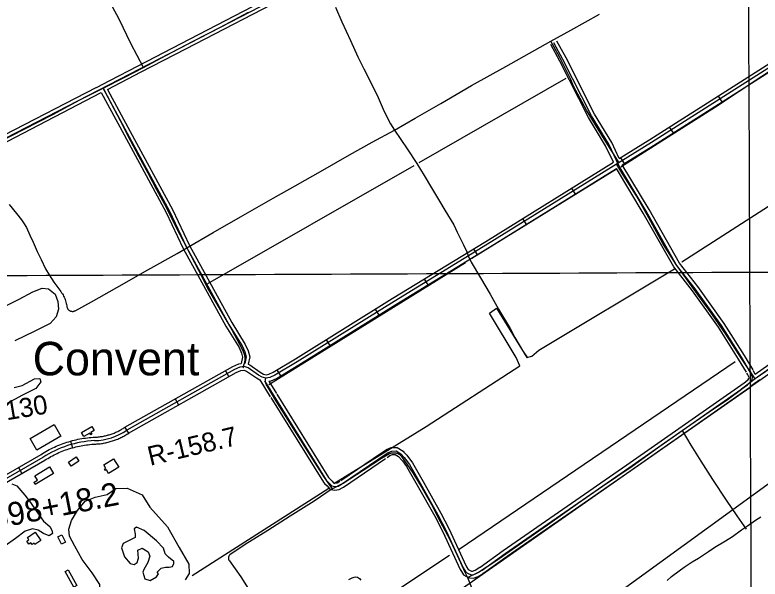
# Model space of a CAD drawing. Extents: x 3419139 to 3457078, y 540382 to 565875.
# Drawn here: x 3441162 to 3444391, y 550592 to 553037 of the extents above; entities that cross this region are included whole.
import ezdxf

# ---------------------------------------------------------------- set-up
doc = ezdxf.new("R2010")
doc.units = 0
for name, color, linetype in [('V-BLDG-OTLN', 7, 'Continuous'), ('V-DTCH-CNTR', 7, 'Continuous'), ('V-GRID-MAJR', 7, 'Continuous'), ('V-RIVR-RANG-IDEN', 7, 'Continuous'), ('V-ROAD-CNTR', 7, 'Continuous'), ('V-SITE-VEGE', 7, 'Continuous'), ('V-SURV-IDEN', 7, 'Continuous'), ('V-TOPO-GNAM-IDEN', 7, 'Continuous'), ('V-TOPO-SHOR', 7, 'Continuous')]:
    doc.layers.add(name, color=color, linetype=linetype)

msp = doc.modelspace()

# ---------------------------------------------------------------- linework, layer by layer
at = {"layer": 'V-BLDG-OTLN'}
for points in [[(3441227.6, 551200.6), (3441332, 551261.8), (3441361.2, 551211.9), (3441256.8, 551150.8)], [(3441450.4, 551226.7), (3441495, 551253.1), (3441505.3, 551235.7), (3441491.3, 551227.4), (3441495.3, 551220.6), (3441490.3, 551217.6), (3441485.9, 551225), (3441460.4, 551209.9)], [(3441393.4, 551098.6), (3441426.8, 551121.5), (3441439, 551103.7), (3441405.5, 551080.9)], [(3441546.7, 551086.4), (3441589.6, 551112.8), (3441612.1, 551076.4), (3441568, 551049.2), (3441558.4, 551064.8), (3441554.6, 551062.4), (3441550.7, 551068.6), (3441555.8, 551071.7)], [(3441248.2, 551039.8), (3441312.4, 551077.9), (3441329.3, 551049.4), (3441250.3, 551002.6), (3441244.9, 551011.7), (3441259.6, 551020.5)], [(3441215.9, 550772), (3441249, 550794.7), (3441273.6, 550758.9), (3441248.5, 550741.7), (3441244.8, 550747.1), (3441236.3, 550741.3), (3441230.6, 550749.6), (3441222.3, 550743.8), (3441214, 550756), (3441222.8, 550762)], [(3441365.3, 550783.1), (3441380.5, 550751.7), (3441363.6, 550743.5), (3441348.4, 550775)], [(3441393.1, 550631.6), (3441430.2, 550564.1), (3441417.2, 550556.9), (3441380.2, 550624.4)]]:
    msp.add_lwpolyline(points, close=True, dxfattribs=at)
at = {"layer": 'V-DTCH-CNTR'}
msp.add_line((3444370, 551459.4), (3444311.2, 551415), dxfattribs=at)
for points in [[(3441718.4, 552809.6), (3441664, 552912.9), (3441613, 553018.9), (3441556.2, 553127.4), (3441520.5, 553196), (3441525.6, 553201.3), (3441530.6, 553206.7), (3441535.4, 553212.3), (3441540.1, 553217.9), (3441544.6, 553223.7), (3441548.9, 553229.7), (3441553.1, 553235.7), (3441557.1, 553241.8), (3441561, 553248.1), (3441564.6, 553254.5), (3441568.1, 553260.9), (3441571.4, 553267.5), (3441574.5, 553274.1), (3441577.5, 553280.9)], [(3442551.4, 553070.8), (3442579.2, 553007.1), (3442615.7, 552925.7), (3442647.4, 552855.6), (3442674, 552803.6), (3442703.2, 552747.5), (3442735.5, 552678.8), (3442761.5, 552617.8), (3442789.6, 552565), (3442806.8, 552537.6), (3442861.5, 552456.5), (3442903.8, 552393), (3442935.2, 552340.5), (3442967.2, 552287.7), (3443001.7, 552229.6), (3443025.6, 552191.1), (3443063.3, 552127.6), (3443079, 552095.1), (3443105.9, 552040.5), (3443120.4, 552009.5), (3443127.5, 551989.6), (3443139.2, 551965.6), (3443180, 551897.2), (3443221.7, 551826.5), (3443257.7, 551762.4), (3443307.5, 551677.4), (3443327.7, 551639.4), (3443361, 551582.6), (3443382.7, 551551.3)], [(3441101.3, 552489.6), (3441201.9, 552541.3), (3441325.8, 552605.9), (3441442.5, 552668.5), (3441543.7, 552719.2), (3441635.8, 552766.3), (3441718.4, 552809.6), (3441815.3, 552860.9), (3441934.8, 552923.5), (3442052.3, 552983.6), (3442174.8, 553048.5)], [(3442611.9, 552430.3), (3442710.5, 552484.9), (3442806.8, 552537.6), (3442896.5, 552588.9), (3443006.9, 552653.4), (3443140.3, 552730.9), (3443288.8, 552813.2), (3443414.6, 552883.5), (3443485, 552922.4), (3443570.4, 552970.4), (3443694.7, 553040.1)], [(3443781.1, 552395.7), (3443716.2, 552497.3), (3443638.4, 552623.8), (3443583.2, 552728.4), (3443570.5, 552756.6), (3443559.1, 552780), (3443522.3, 552855.5), (3443485, 552922.4)], [(3441543.7, 552719.2), (3441578.7, 552652.8), (3441617.6, 552579.7), (3441661.6, 552493.6), (3441698.7, 552423.2), (3441737.3, 552351.9), (3441775.3, 552280.7), (3441819, 552200.6), (3441861.2, 552116.3), (3441907.1, 552026.8), (3441956.8, 551930.7), (3441995.7, 551855.2), (3442051.8, 551758.4), (3442101.6, 551672.6), (3442135.4, 551610.1), (3442149.3, 551581.9), (3442151.1, 551578.2), (3442152.7, 551574.4), (3442154.2, 551570.6), (3442155.4, 551566.6), (3442156.4, 551562.6), (3442157.1, 551558.6), (3442157.7, 551554.5), (3442158, 551550.3), (3442158.1, 551546.2), (3442158, 551542.1), (3442157.6, 551538), (3442157, 551533.9), (3442156.2, 551529.9), (3442155.2, 551525.9), (3442154, 551521.9), (3442150, 551506.5)], [(3441136.4, 552215.4), (3441168.1, 552176.9), (3441190.2, 552149), (3441198.6, 552136.5), (3441211.9, 552116.2), (3441226.7, 552082.3), (3441240.5, 552051.4), (3441258, 552012.3), (3441275.2, 551976.8), (3441295, 551936.2), (3441309.8, 551910.7), (3441330.9, 551878), (3441361.1, 551837.6), (3441364.4, 551833), (3441367.4, 551828.3), (3441370.3, 551823.4), (3441372.9, 551818.5), (3441375.4, 551813.4), (3441377.6, 551808.3), (3441379.7, 551803), (3441381.5, 551797.7), (3441383.2, 551792.3), (3441384.6, 551786.9), (3441385.7, 551781.3), (3441386.7, 551775.8), (3441386.9, 551773.6), (3441387.2, 551771.3), (3441387.8, 551769.1), (3441388.5, 551767), (3441389.5, 551765), (3441390.6, 551763), (3441391.9, 551761.2), (3441393.4, 551759.5), (3441395, 551757.9), (3441396.8, 551756.5), (3441398.7, 551755.3), (3441400.7, 551754.3), (3441402.7, 551753.4), (3441404.9, 551752.7), (3441407.1, 551752.3), (3441409.3, 551752), (3441411.6, 551752), (3441413.8, 551752.1), (3441416.1, 551752.5), (3441418.2, 551753.1), (3441420.4, 551753.9), (3441422.4, 551754.8), (3441493.9, 551794), (3441603.4, 551856.1), (3441738.3, 551931.8), (3441865.3, 552003.6), (3441907.1, 552026.8), (3442020.8, 552094.4), (3442139, 552162.2), (3442280.3, 552243), (3442376.1, 552296.1), (3442495.8, 552364.6), (3442611.9, 552430.3)], [(3444310.4, 551548.5), (3444244.9, 551648.3), (3444178.8, 551745.7), (3444113, 551836.2), (3444026.9, 551954.8), (3443970.2, 552046.4), (3443908.6, 552157.4), (3443855, 552252.9), (3443788, 552360.3), (3443770.4, 552388.5)], [(3445088.4, 551970.4), (3444921.6, 551847), (3444726.4, 551708.8), (3444536.4, 551573.4), (3444370, 551459.4), (3444310.4, 551548.5)], [(3442247.9, 551463), (3442247.3, 551459.9), (3442246.9, 551456.8), (3442246.7, 551453.7), (3442246.7, 551450.6), (3442247, 551447.4), (3442247.5, 551444.3), (3442248.2, 551441.3), (3442249.1, 551438.2), (3442250.1, 551435.3), (3442251.4, 551432.4), (3442252.9, 551429.7), (3442290.7, 551366.6), (3442336.5, 551294.4), (3442382.7, 551221.3), (3442441.2, 551126.9), (3442501.9, 551032), (3442537.2, 550982.5)], [(3443123.1, 550598.3), (3443171, 550622.1), (3443245.9, 550671.3), (3443361.2, 550751.6), (3443469.8, 550826.5), (3443600, 550918.9), (3443708.6, 550994.6), (3443836.9, 551081.9), (3443962.5, 551171.9), (3444053.3, 551235.3), (3444171, 551317.4), (3444248, 551369.3), (3444311.2, 551415)], [(3444053.3, 551235.3), (3444091.3, 551172.2), (3444134.4, 551102.7), (3444185.1, 551022.9), (3444243.4, 550934.6), (3444290.2, 550865.5), (3444331.2, 550807.8)], [(3442537.2, 550982.5), (3442584.5, 551007.6), (3442671.3, 551064), (3442750.2, 551115.6), (3442785.4, 551135.8), (3442788.2, 551137), (3442791, 551137.9), (3442794, 551138.7), (3442796.9, 551139.3), (3442799.9, 551139.6), (3442803, 551139.8), (3442806, 551139.7), (3442809, 551139.4), (3442812, 551138.9), (3442815, 551138.2), (3442817.8, 551137.3), (3442820.7, 551136.2), (3442823.4, 551134.9), (3442826.1, 551133.5), (3442828.6, 551131.8), (3442831, 551130), (3442833.3, 551128), (3442835.4, 551125.9), (3442837.4, 551123.6), (3442886, 551052), (3442926.2, 550985.3), (3442967.2, 550914.9), (3443005.2, 550842.1), (3443048, 550760.2), (3443078.2, 550695.9), (3443113.1, 550619.8), (3443123.1, 550598.3), (3443149.3, 550533.4)], [(3442537.2, 550982.5), (3442459.3, 550930), (3442354.6, 550864.2), (3442257.2, 550802.1), (3442159.6, 550742), (3442093.1, 550696.4), (3442091.8, 550695.1), (3442090.6, 550693.6), (3442089.5, 550692), (3442088.7, 550690.4), (3442088, 550688.6), (3442087.5, 550686.8), (3442087.2, 550684.9), (3442087.1, 550683), (3442087.2, 550681.1), (3442087.5, 550679.3), (3442088, 550677.4), (3442088.7, 550675.7), (3442089.6, 550674), (3442090.6, 550672.4), (3442091.8, 550671), (3442141.4, 550601.8), (3442209, 550493.2)]]:
    msp.add_lwpolyline(points, dxfattribs=at)
at = {"layer": 'V-GRID-MAJR'}
for points in [[(3444374.2, 545864.2), (3444346.9, 551922.1), (3444319.6, 557983), (3444292.3, 564044), (3444292.3, 564047.1)], [(3423248.5, 551833.1), (3428523.1, 551854.2), (3433797.7, 551876), (3439072.3, 551898.7), (3444346.9, 551922.1), (3449621.5, 551946.2), (3454896.1, 551971.2)]]:
    msp.add_spline(points, degree=3, dxfattribs=at)
at = {"layer": 'V-ROAD-CNTR'}
for p, q in [((3444208.8, 552684.8), (3444224.9, 552659.5)), ((3443997.8, 552550.8), (3444013.9, 552525.5)), ((3443786.1, 552418.1), (3443801.9, 552392.6)), ((3443573.7, 552286.2), (3443589.5, 552260.7)), ((3443361.4, 552154.3), (3443377.2, 552128.8)), ((3443148.9, 552022.8), (3443164.5, 551997.2)), ((3442935.6, 551892.2), (3442951.3, 551866.6)), ((3442722.7, 551761.1), (3442738.5, 551735.6)), ((3442510.4, 551629.1), (3442526.2, 551603.6)), ((3442074.7, 551495.1), (3442089.4, 551468.9)), ((3442297.5, 551498.4), (3442313, 551472.7)), ((3441856.7, 551372.6), (3441871.4, 551346.5)), ((3441637.9, 551249.6), (3441654.4, 551224.5)), ((3441402.6, 551189.7), (3441410.9, 551160.9)), ((3441177, 551075.6), (3441191.9, 551049.6))]:
    msp.add_line(p, q, dxfattribs=at)
for points in [[(3440402.9, 552124.1), (3440507.2, 552176.7), (3440773.2, 552319.9), (3441124.3, 552503.6), (3441702.7, 552803.1), (3442354.1, 553141.8), (3442536.9, 553238.4), (3443478, 553732.7), (3443595, 553790.8), (3443627.4, 553808.3), (3443649.5, 553821.1), (3443677.3, 553837.9), (3443718.1, 553854.3), (3443741, 553863.2), (3443750.8, 553864.7), (3443777.8, 553858.9), (3443799.3, 553857), (3443824.1, 553860.9), (3443863.9, 553877.1), (3444191.1, 554049.6), (3444959.7, 554457.4)], [(3441882.7, 552913.6), (3442347.1, 553155.1), (3442452.5, 553210.8)], [(3441902, 552889.8), (3442361, 553128.5), (3442470.8, 553186.5)], [(3444672.4, 552958.2), (3444627.2, 552932.6), (3443921.1, 552484.3), (3443210.2, 552042.7), (3442804.9, 551794.6), (3442385, 551533.5), (3442287.9, 551475.1), (3442267.2, 551465), (3442249.5, 551462.2), (3442233.8, 551466.4), (3442216.9, 551476.2), (3442172.9, 551506.9), (3442154.8, 551513.3), (3442136.1, 551510.8), (3442113.9, 551499.9), (3441646.5, 551237.3)], [(3443780.9, 552414.9), (3443913.1, 552497), (3444619.5, 552945.5), (3444665.1, 552971.3)], [(3443780.9, 552414.9), (3443748.4, 552484.4), (3443673.2, 552607.1), (3443550.2, 552850.5), (3443510.3, 552922.9)], [(3443793.7, 552387.5), (3443929.1, 552471.6), (3444634.9, 552919.8), (3444646, 552926.1)], [(3444656.9, 552936.8), (3444863.5, 552624.4), (3444906.6, 552562.5), (3444919.8, 552534.7), (3444939.2, 552465), (3444956.1, 552401.2), (3444959.3, 552369.1), (3444959.6, 552320.2), (3444958.3, 552277.1), (3444959.5, 552238.4), (3444967.8, 552209.9), (3444979.4, 552184.2), (3444997.9, 552153), (3445023.4, 552116.1), (3445060.2, 552075.1), (3445096.4, 552027.9), (3445108, 552010.1), (3445108.5, 552002.8), (3445107.6, 551992.6), (3445102, 551981.2), (3445070.9, 551955.5), (3444370.4, 551459.9)], [(3441572.7, 552752.7), (3441695.8, 552816.4), (3441882.7, 552913.6)], [(3442243.2, 551451.5), (3442511, 551021.1), (3442525.3, 551005.9), (3442535.2, 550995.7), (3442547.2, 550992.6), (3442562.6, 550995.1), (3442577.6, 551003.2), (3442779.7, 551140.3), (3442795.3, 551146.8), (3442814.5, 551147.1), (3442834.2, 551134.9), (3442849.1, 551119.1), (3442871.9, 551088.2), (3442918.1, 551007), (3442994.1, 550871.1), (3443029.4, 550803.9), (3443104.4, 550640.3), (3443116.1, 550622.1), (3443125.6, 550616.9), (3443136.2, 550612.3), (3443147.3, 550610.7), (3443163, 550617), (3443186.1, 550631.1), (3443286.9, 550703), (3443821.7, 551074.6), (3444336.7, 551434.3), (3444350.5, 551446.5), (3444356.9, 551456.4), (3444358.7, 551467.6), (3444349.8, 551487.5), (3444310.9, 551553.2), (3444223.7, 551691.5), (3444109.5, 551850.2), (3444029.2, 551953), (3443898, 552185.7), (3443780, 552381.3), (3443735.2, 552477.3), (3443660.1, 552599.8), (3443536.9, 552843.5), (3443497.2, 552915.7)], [(3443755.2, 552398.9), (3443721.9, 552470.2), (3443647, 552592.5), (3443523.6, 552836.5), (3443484, 552908.5)], [(3441562.9, 552713.8), (3441709.6, 552789.8), (3441902, 552889.8)], [(3441515.2, 552722.9), (3441572.7, 552752.7)], [(3441105.3, 552510.6), (3441117.4, 552517), (3441514, 552722.3)], [(3441121.1, 552485), (3441131.2, 552490.3), (3441536.2, 552700)], [(3441536.2, 552700), (3441635.5, 552517.4), (3441818, 552180.3), (3441891.7, 552024.1), (3442076.6, 551688.4), (3442133.5, 551595.1), (3442144.2, 551571.4), (3442148.5, 551554.2), (3442142.5, 551526.8)], [(3441542.4, 552720.1), (3441648.7, 552524.6), (3441831.3, 552187), (3441905.1, 552030.9), (3442089.5, 551695.9), (3442146.8, 551602.1), (3442158.4, 551576.3), (3442163.9, 551554.5), (3442157.6, 551525.8)], [(3441562.9, 552713.8), (3441661.9, 552531.7), (3441844.7, 552193.8), (3441918.5, 552037.7), (3442102.5, 551703.4), (3442160.1, 551609.1), (3442172.6, 551581.3), (3442179.3, 551554.7), (3442172.3, 551523)], [(3442172.3, 551523), (3442179.8, 551520.4), (3442225, 551488.9), (3442239.6, 551480.4), (3442250.3, 551477.5), (3442262.6, 551479.4), (3442280.7, 551488.3), (3442377.2, 551546.3), (3442797, 551807.3), (3443202.4, 552055.5), (3443755.2, 552398.9)], [(3444361, 551498.1), (3444323.7, 551561), (3444236.1, 551699.8), (3444121.5, 551859.3), (3444041.7, 551961.3), (3443911, 552193.2), (3443793.7, 552387.5)], [(3442262.5, 551449), (3442271.8, 551450.5), (3442295, 551461.9), (3442392.8, 551520.7), (3442812.8, 551781.8), (3443218.1, 552030), (3443768.2, 552371.7)], [(3444331.6, 551488.8), (3444298.1, 551545.3), (3444211.2, 551683.1), (3444097.5, 551841.2), (3444016.7, 551944.6), (3443885, 552178.1), (3443768.2, 552371.7)], [(3445072.2, 551976.1), (3445061.8, 551967.4), (3444380.3, 551485.3)], [(3440700.3, 550801.3), (3441275.5, 551132.3), (3441282.1, 551136.6), (3441289.2, 551140.8), (3441296.3, 551145), (3441303.5, 551149.1), (3441310.9, 551153), (3441318.1, 551156.7), (3441325.6, 551160.4), (3441333.1, 551164), (3441340.6, 551167.4), (3441348.2, 551170.6), (3441355.9, 551173.7), (3441363.5, 551176.8), (3441371.4, 551179.7), (3441379.2, 551182.4), (3441387, 551185), (3441394.9, 551187.4), (3441402.8, 551189.8), (3441410.8, 551191.9), (3441418.9, 551194), (3441426.9, 551195.9), (3441435, 551197.7), (3441443.1, 551199.3), (3441451.2, 551200.7), (3441459.4, 551202.1), (3441467.6, 551203.3), (3441475.8, 551204.3), (3441484, 551205.2), (3441492.3, 551206), (3441500.5, 551206.6), (3441505.8, 551206.9), (3441510.4, 551207.1), (3441514.8, 551207.4), (3441519.2, 551207.7), (3441523.6, 551208.1), (3441527.9, 551208.6), (3441532.3, 551209.2), (3441536.6, 551209.8), (3441540.9, 551210.5), (3441545.2, 551211.3), (3441549.6, 551212.2), (3441553.9, 551213.2), (3441558.1, 551214.2), (3441562.4, 551215.3), (3441566.6, 551216.4), (3441570.8, 551217.7), (3441575, 551219), (3441579.2, 551220.4), (3441583.3, 551221.9), (3441587.4, 551223.4), (3441591.5, 551225), (3441595.6, 551226.7), (3441599.6, 551228.4), (3441603.6, 551230.2), (3441607.5, 551232.1), (3441611.5, 551234.1), (3441615.4, 551236.1), (3441619.3, 551238.2), (3441623.1, 551240.3), (3441626.8, 551242.6), (3441630.6, 551244.9), (3441634.3, 551247.2), (3441637.8, 551249.5), (3441638.4, 551250), (3442106.9, 551513.1), (3442131.7, 551525.3), (3442142.5, 551526.8)], [(3440715.3, 550775.3), (3441291, 551106.7), (3441297.9, 551111.1), (3441304.5, 551115), (3441311.2, 551118.9), (3441318, 551122.8), (3441324.8, 551126.4), (3441331.7, 551130), (3441338.7, 551133.4), (3441345.6, 551136.7), (3441352.7, 551139.9), (3441359.8, 551143), (3441367, 551145.9), (3441374.2, 551148.8), (3441381.5, 551151.4), (3441388.8, 551154), (3441396.2, 551156.4), (3441403.6, 551158.7), (3441411, 551160.9), (3441418.5, 551162.9), (3441426, 551164.8), (3441433.5, 551166.6), (3441441.1, 551168.3), (3441448.7, 551169.8), (3441456.3, 551171.2), (3441464, 551172.4), (3441471.6, 551173.5), (3441479.4, 551174.5), (3441487.1, 551175.4), (3441494.7, 551176.1), (3441502.5, 551176.7), (3441507.3, 551177), (3441512, 551177.1), (3441516.9, 551177.4), (3441521.7, 551177.8), (3441526.6, 551178.3), (3441531.6, 551178.8), (3441536.4, 551179.5), (3441541.3, 551180.2), (3441546.1, 551181), (3441551, 551181.9), (3441555.8, 551182.9), (3441560.5, 551183.9), (3441565.3, 551185.1), (3441570.1, 551186.3), (3441574.9, 551187.6), (3441579.5, 551189), (3441584.2, 551190.5), (3441588.9, 551192), (3441593.5, 551193.7), (3441598.2, 551195.4), (3441602.7, 551197.2), (3441607.3, 551199), (3441611.8, 551201), (3441616.2, 551203), (3441620.7, 551205.1), (3441625.1, 551207.3), (3441629.4, 551209.6), (3441633.7, 551211.9), (3441638.1, 551214.3), (3441642.3, 551216.9), (3441646.5, 551219.4), (3441650.6, 551222), (3441654.9, 551224.8), (3441654.6, 551224.7), (3442120.9, 551486.6), (3442140.5, 551496.2), (3442153.2, 551497.9), (3442166, 551493.4), (3442208.9, 551463.6), (3442223.3, 551455.2)], [(3444322.2, 551442.5), (3444327.4, 551446.1), (3444339, 551456.4), (3444342.6, 551461.9), (3444343.2, 551465.6), (3444336.5, 551480.6), (3444333.9, 551484.9)], [(3444370.4, 551478.3), (3444363.2, 551494.4), (3444362.3, 551495.8)], [(3444380.3, 551485.3), (3444370.4, 551478.3)], [(3442223.3, 551455.2), (3442268.5, 551382.5)], [(3442262.5, 551449), (3442295.7, 551395.6)], [(3443177, 550643.1), (3443177.8, 550643.6), (3443278.3, 550715.3), (3443813.1, 551086.9), (3444322.2, 551442.5)], [(3444389.8, 551455.3), (3444355.8, 551431.2)], [(3443187.2, 550614.2), (3443194.3, 550618.6), (3443295.6, 550690.7), (3443830.3, 551062.3), (3444346, 551422.5), (3444355.8, 551431.2)], [(3442270.9, 551378.7), (3442499, 551012), (3442503.9, 551006.8)], [(3442297.2, 551393.2), (3442521.3, 551032.9)], [(3442750.9, 551138.9), (3442772.5, 551153.6), (3442792.2, 551161.7), (3442818.7, 551162.1), (3442843.8, 551146.6), (3442847.8, 551142.3)], [(3441283.2, 551119.5), (3440707.8, 550788.3)], [(3442574, 551018.9), (3442750.9, 551138.9)], [(3442774.6, 551118.7), (3442786.9, 551127), (3442798.4, 551131.8), (3442810.3, 551132), (3442824.7, 551123.1), (3442837.6, 551109.5), (3442841.4, 551104.2)], [(3442847.8, 551142.3), (3442860.7, 551128.7), (3442884.5, 551096.4), (3442931.1, 551014.4), (3443007.3, 550878.3), (3443042.9, 550810.5), (3443117.6, 550647.5), (3443119.2, 550645)], [(3442580.6, 550987.8), (3442585.4, 550990.4), (3442767.5, 551113.9)], [(3442841.4, 551104.2), (3442859.3, 551080), (3442905, 550999.7), (3442980.9, 550864), (3443015.9, 550797.3), (3443091.2, 550633.1), (3443096.5, 550624.8)], [(3442521.3, 551032.9), (3442522.9, 551030.3), (3442536.2, 551016.3), (3442543, 551009.2), (3442547.9, 551007.9), (3442557.7, 551009.5), (3442569.8, 551016.1), (3442570.4, 551016.4)], [(3442503.9, 551006.8), (3442514.4, 550995.6), (3442527.3, 550982.2), (3442546.6, 550977.3), (3442567.5, 550980.7), (3442580.6, 550987.8)], [(3443119.2, 550645), (3443126.6, 550633.5), (3443132.2, 550630.4), (3443140.4, 550626.9), (3443145.5, 550626.1), (3443156.3, 550630.4), (3443177, 550643.1)], [(3443096.5, 550624.8), (3443105.5, 550610.8), (3443119, 550603.4), (3443132.1, 550597.8), (3443149.1, 550595.3), (3443169.7, 550603.5), (3443183.4, 550611.9)]]:
    msp.add_lwpolyline(points, dxfattribs=at)
for centre, radius, start, end in [((3441497.5, 551458.3), 266.6, 271.9381, 303.988), ((3441531.8, 550733.6), 459, 93.1576, 122.7888)]:
    msp.add_arc(centre, radius, start, end, dxfattribs=at)
at = {"layer": 'V-SITE-VEGE'}
for p, q in [((3444371.8, 550847.3), (3444394.6, 550861.6)), ((3444336, 550822.1), (3444371.8, 550847.3)), ((3444271, 550777), (3444310.2, 550804.8)), ((3444310.2, 550804.8), (3444336, 550822.1)), ((3444241.2, 550757.8), (3444271, 550777)), ((3444167.2, 550711.5), (3444194.5, 550730.3)), ((3444194.5, 550730.3), (3444241.2, 550757.8)), ((3444124.7, 550683.3), (3444167.2, 550711.5)), ((3444061.6, 550643.5), (3444097.4, 550666.4)), ((3444097.4, 550666.4), (3444124.7, 550683.3)), ((3444040.3, 550627.7), (3444061.6, 550643.5)), ((3443988.8, 550585.3), (3444007.9, 550602.5)), ((3444007.9, 550602.5), (3444040.3, 550627.7))]:
    msp.add_line(p, q, dxfattribs=at)
for points in [[(3441113.7, 551771.3), (3441180.9, 551805.6), (3441239, 551836.9), (3441280.1, 551852.5), (3441307.3, 551850), (3441336.2, 551826.4), (3441347.6, 551795.5), (3441351.2, 551762.3), (3441340.8, 551728.5), (3441314.8, 551698.9), (3441247.6, 551665.8), (3441161.7, 551624.9)], [(3441158.2, 551421.9), (3441193.3, 551430.9), (3441246.5, 551460.4), (3441269.5, 551460.9), (3441273.7, 551447), (3441252.5, 551417.5), (3441195, 551389.2), (3441106.1, 551341.7)], [(3441148.6, 551005), (3441169.8, 550995.8), (3441204.9, 550956.3), (3441229.8, 550924), (3441253.4, 550887.5), (3441286.1, 550843.1), (3441312.7, 550820), (3441321.8, 550804.2), (3441324.8, 550789), (3441310.8, 550779.9), (3441285.3, 550789.7), (3441262.9, 550804.3), (3441238.6, 550809.8), (3441206.4, 550799.6), (3441165, 550768.1), (3441119.4, 550735.4)], [(3441395.9, 550808.8), (3441407.5, 550845.9), (3441433.1, 550888.9), (3441466, 550930.1), (3441509.2, 550947), (3441562.1, 550958.5), (3441599.2, 550983.9), (3441649, 550985.6), (3441712.7, 550956.9), (3441747.2, 550904), (3441823.5, 550818.8), (3441873.1, 550729.4), (3441915.4, 550656.4), (3441916.5, 550616.9), (3441900.1, 550588.4)], [(3441121, 550376.5), (3441167.8, 550395.8), (3441198.1, 550386), (3441247.3, 550387.1), (3441264.4, 550401), (3441254.1, 550424.1), (3441243.8, 550443), (3441248.1, 550453.3), (3441277.9, 550454.4), (3441307.6, 550435.5), (3441373.8, 550457.9), (3441443.2, 550504.5), (3441529.5, 550549.8), (3441529.6, 550569.2), (3441496.9, 550618.5), (3441453.3, 550676.3), (3441421.2, 550734.1), (3441398.9, 550777.9), (3441395.9, 550808.8)], [(3442608.4, 550590), (3442623.3, 550597), (3442632.4, 550600.4), (3442639.9, 550601.7), (3442646.8, 550600.4), (3442654.7, 550594.3), (3442660.3, 550587.7)]]:
    msp.add_lwpolyline(points, dxfattribs=at)
msp.add_lwpolyline([(3441778.1, 550622.7), (3441795.7, 550639.7), (3441814.6, 550643.9), (3441831, 550643.8), (3441844.9, 550646.8), (3441851, 550659), (3441850.5, 550668.7), (3441828, 550686.4), (3441813.5, 550701.6), (3441805.7, 550725.3), (3441776, 550758.2), (3441722, 550802), (3441689.3, 550817.3), (3441678.9, 550809.4), (3441682.5, 550786.3), (3441683.7, 550771.7), (3441631.4, 550746.3), (3441624.1, 550728.1), (3441636.1, 550688.6), (3441661, 550660), (3441678.6, 550655.1), (3441691.3, 550663.6), (3441698.1, 550683), (3441694.5, 550717.7), (3441712.7, 550726.1), (3441740, 550709.6), (3441746.1, 550692), (3441738.1, 550664.1), (3441720.4, 550633.8), (3441716.1, 550621.6), (3441724.6, 550592.5), (3441747.6, 550585.7), (3441775.6, 550602.1), (3441783.5, 550615.4)], close=True, dxfattribs=at)
at = {"layer": 'V-TOPO-SHOR'}
for p, q in [((3442914, 552397.4), (3443550.3, 552762.1)), ((3444051.8, 551967.5), (3444878.8, 552497.9)), ((3441997.9, 551873.2), (3442891.5, 552383.8)), ((3443142, 551982.2), (3443769.2, 552369.5)), ((3442262.2, 551435.5), (3443115, 551964)), ((3443087.1, 550722), (3444283.2, 551535.6)), ((3441929.7, 550607.4), (3442522.7, 550985.5))]:
    msp.add_line(p, q, dxfattribs=at)
for points in [[(3443787.3, 552378.6), (3444197.8, 552638.3), (3444603.8, 552907)], [(3442543.4, 551006.4), (3442944, 551253.3), (3443349.7, 551515.9), (3443333.9, 551552.3), (3443218.3, 551744.8), (3443249.5, 551765.8), (3443380.8, 551552.5), (3443401.6, 551557.8), (3443432.8, 551584.1), (3444020.7, 551936.1)], [(3442697.9, 550271.7), (3444081.1, 551237.4), (3444845.4, 551772.8)], [(3445259.7, 551584.9), (3444468.3, 551033.4), (3442348.7, 549495.1), (3441176.2, 548639.4)], [(3442734.8, 550178), (3442587.9, 550391.2), (3443045.5, 550695.7)]]:
    msp.add_lwpolyline(points, dxfattribs=at)

# ---------------------------------------------------------------- texts
at = {"layer": 'V-RIVR-RANG-IDEN'}
for s, rotation, p in [('D-130', 9.3943, (3441010.6, 551260.9)), ('R-158.7', 13.4032, (3441747.9, 551082.7))]:
    msp.add_text(s, height=83, rotation=rotation, dxfattribs=at).set_placement(p)
at = {"layer": 'V-SURV-IDEN'}
msp.add_text('3598+18.2', height=100, rotation=11.1461, dxfattribs=at).set_placement((3440995.1, 550792.4))
at = {"layer": 'V-TOPO-GNAM-IDEN'}
msp.add_text('Convent', height=145, dxfattribs=at).set_placement((3441238.9, 551474.9))

doc.saveas('drawing.dxf')
